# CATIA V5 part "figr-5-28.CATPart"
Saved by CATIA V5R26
Part number: Part1
Bounding box of the stored display mesh (mm): x -100 to 100, y -100 to 100, z 0 to 57
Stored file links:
  D:\_Deepak\CATIA\CATIA V5-6R2016_Deepak\Resources\Part files\Partfiles\c05_catia_v5_6r2016_prt\figr-5-28.CATPart
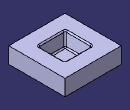
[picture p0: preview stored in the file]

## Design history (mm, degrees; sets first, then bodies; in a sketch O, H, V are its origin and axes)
Body1 (main body)
  Sketch1 on xy-plane, origin (0, 0, 0), H (1, 0, 0), V (0, 1, 0)
    line L1 (-100, 100) -> (100, 100)
    line L2 (100, 100) -> (100, -100)
    line L3 (100, -100) -> (-100, -100)
    line L4 (-100, -100) -> (-100, 100)
    axis line L5 (100, -100) -> (-100, 100)
    length L3 = 200
    length L2 = 200
    horizontal: L1 H, L3 H
    vertical: L2 V, L4 V
    midpoint: L5 O
  Pad1: profile Sketch1, direction (0, 0, 1), length 57
  Sketch2 on face of Pad1, origin (0, 0, 57), H (1, 0, 0), V (0, 1, 0)
    line L1 (-48.5141, 47.7936) -> (48.5141, 47.7936)
    line L2 (48.5141, 47.7936) -> (48.5141, -47.7936)
    line L3 (48.5141, -47.7936) -> (-48.5141, -47.7936)
    line L4 (-48.5141, -47.7936) -> (-48.5141, 47.7936)
    axis line L5 (48.5141, -47.7936) -> (-48.5141, 47.7936)
    horizontal: L1 H, L3 H
    vertical: L2 V, L4 V
    midpoint: O L5
  Pocket1: profile Sketch2, direction (0, 0, -1), length 42, opposite side up to face of Pad1
  Draft1: Angle 15, Neutral face of Pad1, PullDir face of Pocket1, SupportToDraft (face of Pocket1; face of Pocket1; face of Pocket1; face of Pocket1)
  Fillet1: radius 5, on edge [face of Pocket1 | face of Pocket1] (x4)
  Fillet2: radius 5, on edge [face of Pocket1 | face of Pocket1] (x4)
  Fillet3: radius 5, on edge [face of Pocket1 | face of Pad1]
